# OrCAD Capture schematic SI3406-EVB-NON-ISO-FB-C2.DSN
size B; title: Si3402 Eval Board - Isolated; rev: 2.1; note: SI3406-EVB-NON-ISO-FB-C2
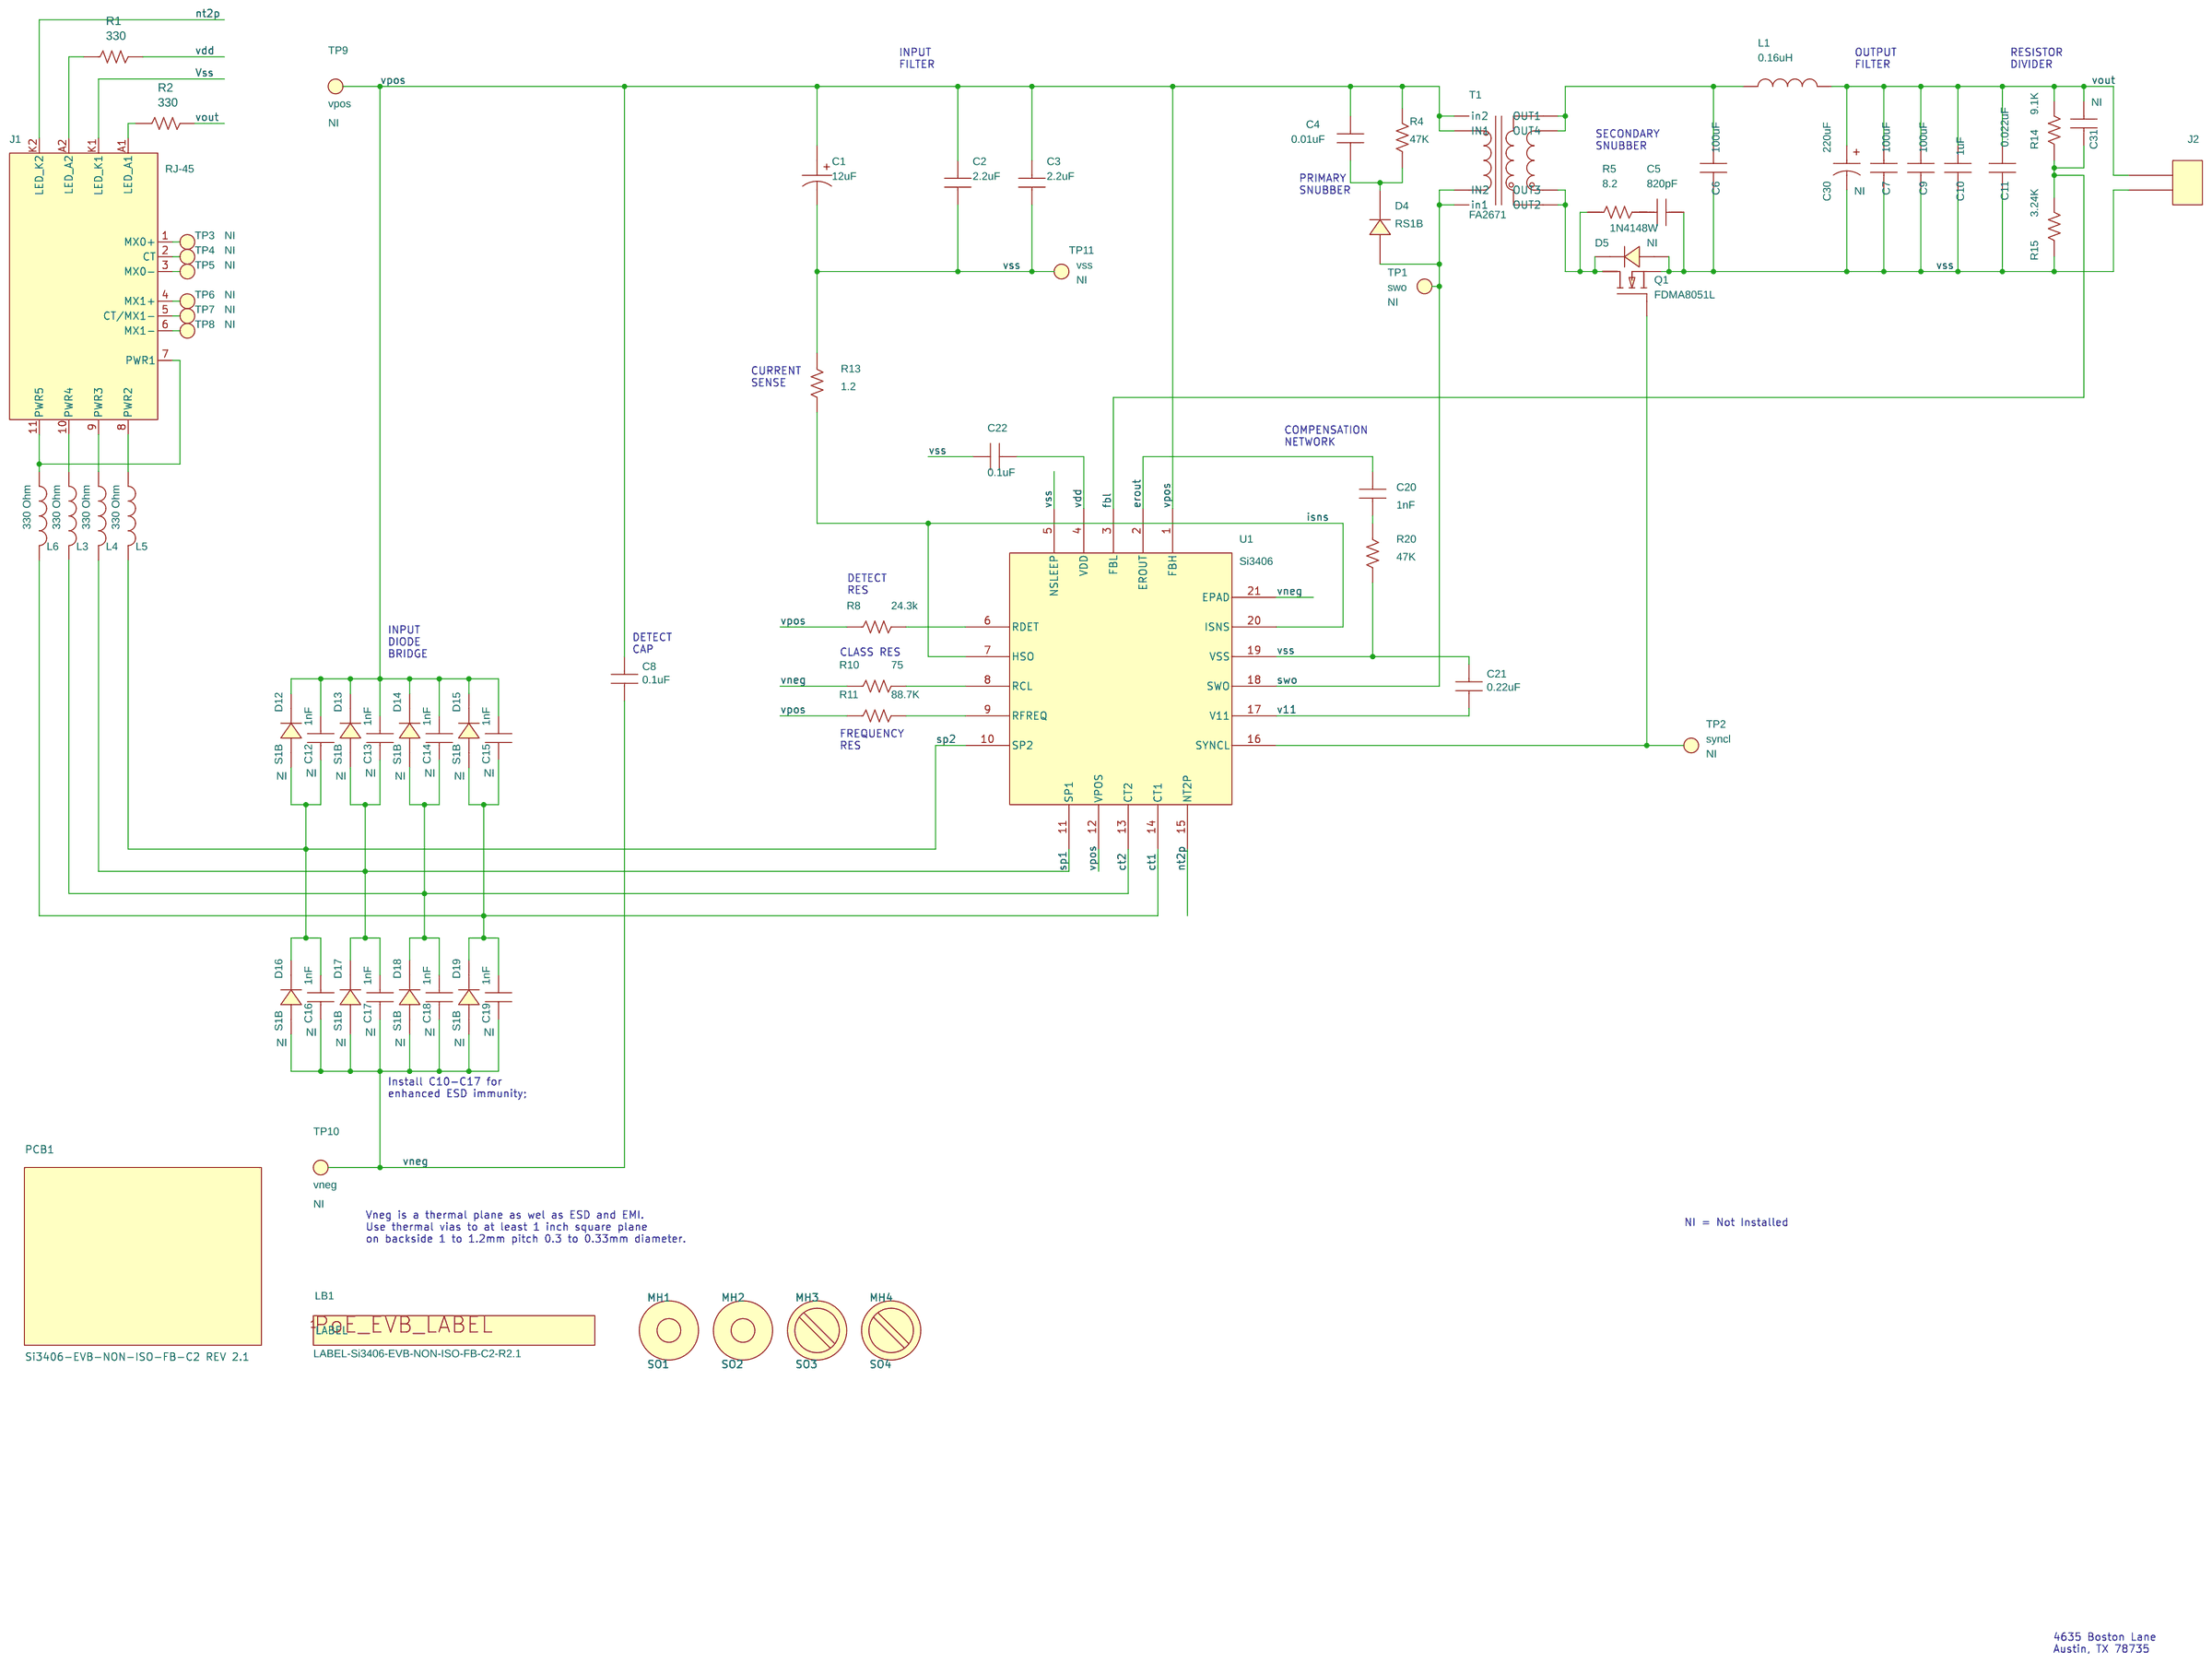
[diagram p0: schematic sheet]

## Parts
C1  12uF  [C2.5X6.3MM-RAD]
C2  2.2uF  [C1210]
C3  2.2uF  [C1210]
C4  0.01uF  [C0805]
C5  820pF  [C0805]
C6  100uF  [C1210]
C7  100uF  [C1210]
C8  0.1uF  [C0805]
C9  100uF  [C1210]
C10  1uF  [C0603]
C11  0.022uF  [C0603]
C12  1nF  [C0603]
C13  1nF  [C0603]
C14  1nF  [C0603]
C15  1nF  [C0603]
C16  1nF  [C0603]
C17  1nF  [C0603]
C18  1nF  [C0603]
C19  1nF  [C0603]
C20  1nF  [C0805]
C21  0.22uF  [C0805]
C22  0.1uF  [C0805]
C30  220uF  [C2X5MM-RAD]
C31  330pF  [C0805]
D4  RS1B  [DO-214AC]
D5  1N4148W  [SOD-123]
D12  S1B  [DO-214AC]
D13  S1B  [DO-214AC]
D14  S1B  [DO-214AC]
D15  S1B  [DO-214AC]
D16  S1B  [DO-214AC]
D17  S1B  [DO-214AC]
D18  S1B  [DO-214AC]
D19  S1B  [DO-214AC]
J1  RJ-45  [RJ45-SI-52004]
J2  CONN TRBLK 2  [CONN-1X2-TB]
L1  0.16uH  [IND-XAL50xx]
L3  330 Ohm  [L0805]
L4  330 Ohm  [L0805]
L5  330 Ohm  [L0805]
L6  330 Ohm  [L0805]
LB1  LABEL-Si3406-EVB-NON-ISO-FB-C2-R2.1  [PTL-14-477]
MH1  4-40  [MH-125NP]
MH2  4-40  [MH-125NP]
MH3  4-40  [MH-125NP]
MH4  4-40  [MH-125NP]
PCB1  Si3406-EVB-NON-ISO-FB-C2 REV 2.1  [N/A]
Q1  FDMA8051L  [DFN6N2X2P0.65E1.0X1.05]
R1  330  [R0805]
R2  330  [R0805]
R4  47K  [R0805]
R5  8.2  [R0805]
R8  24.3k  [R0805]
R10  75  [R0805]
R11  88.7K  [R0805]
R13  1.2  [R0805]
R14  9.1K  [R0805]
R15  3.24K  [R0805]
R20  47K  [R0805]
SO1  STANDOFF
SO2  STANDOFF
SO3  STANDOFF
SO4  STANDOFF
T1  FA2671  [XFMR-FA2671]
TP1  BLUE  [TESTPOINT]
TP2  BLUE  [TESTPOINT]
TP3  BLUE  [TESTPOINT]
TP4  BLUE  [TESTPOINT]
TP5  BLUE  [TESTPOINT]
TP6  BLUE  [TESTPOINT]
TP7  BLUE  [TESTPOINT]
TP8  BLUE  [TESTPOINT]
TP9  BLUE  [TESTPOINT]
TP10  BLUE  [TESTPOINT]
TP11  BLUE  [TESTPOINT]
U1  Si3406  [QFN20N5X5P0.8]

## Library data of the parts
C1 = CAP_POL: CAP, 12uF, 100V, ±20%, AL, 6.3X11.2MM; Manufacturer: Panasonic; ManufacturerPN: EEUFC2A120; Part_Type: CAP/POL; SiLabsPN: EEUFC2A120; Tolerance: ±20%; Type: Alum_Elec; Voltage: 100V; Datasheet: ABA0000CE22.pdf
C2 C3 = CAP_NP: CAP, 2.2uF, 100V, ±10%, X7R, 1210; Manufacturer: Samsung; ManufacturerPN: CL32B225KCJSNNE; SiLabsPN: CL32B225KCJSNNE; Tolerance: ±10%; Type: X7R; Voltage: 100V; Datasheet: MLCC.pdf
C4 = CAP_NP: CAP, 0.01uF, 100V, ±10%, X7R, 0805; Manufacturer: Venkel; ManufacturerPN: C0805X7R101-103K; SiLabsPN: C0805X7R101-103K; Tolerance: ±10%; Type: X7R; Voltage: 100V; Datasheet: PID_C.pdf
C5 = CAP_NP: CAP, 820pF, 50V, ±10%, X7R, 0805; Manufacturer: Yageo; ManufacturerPN: CC0805KRX7R9BB821; SiLabsPN: C0805X7R500-821K; Tolerance: ±10%; Type: X7R; Voltage: 50V; Datasheet: UPY-GPHC_X7R_6.3V-to-50V_18.pdf
C6 C7 C9 = CAP_NP: CAP, 100uF, 6.3V, ±10%, X5R, 1210; Manufacturer: Venkel; ManufacturerPN: C1210X5R6R3-107K; SiLabsPN: C1210X5R6R3-107K; Tolerance: ±10%; Type: X5R; Voltage: 6.3V; Datasheet: PID_C.pdf
C8 C22 = CAP_NP: CAP, 0.1uF, 100V, ±10%, X7R, 0805; Manufacturer: Venkel; ManufacturerPN: C0805X7R101-104K; SiLabsPN: C0805X7R101-104K; Tolerance: ±10%; Type: X7R; Voltage: 100V; Datasheet: PID_C.pdf
C10 = CAP_NP: CAP, 1uF, 6.3V, ±10%, X5R, 0603; Manufacturer: Venkel; ManufacturerPN: C0603X5R6R3-105K; SiLabsPN: C0603X5R6R3-105K; Tolerance: ±10%; Type: X5R; Voltage: 6.3V; Datasheet: PID_C.pdf
C11 = CAP_NP: CAP, 0.022uF, 50V, ±20%, X7R, 0603; Manufacturer: TDK Corporation; ManufacturerPN: C1608X7R1H223M; SiLabsPN: C0603X7R500-223M; Tolerance: ±20%; Type: X7R; Voltage: 50V; Datasheet: general_B11.pdf
C12-C19 = CAP_NP: CAP, 1nF, 100V, ±10%, X7R, 0603; Installed Component: NI; Manufacturer: Venkel; ManufacturerPN: C0603X7R101-102K; SiLabsPN: C0603X7R101-102K; Tolerance: ±10%; Type: X7R; Voltage: 100V; Datasheet: PID_C.pdf
C20 = CAP_NP: CAP, 1nF, 50V, ±1%, C0G, 0805; Manufacturer: Venkel; ManufacturerPN: C0805C0G500-102F; SiLabsPN: C0805C0G500-102F; Tolerance: ±1%; Type: C0G; Voltage: 50V; Datasheet: PID_C.pdf
C21 = CAP_NP: CAP, 0.22uF, 10V, ±10%, X7R, 0805; Manufacturer: Venkel; ManufacturerPN: C0805X7R100-224K; SiLabsPN: C0805X7R100-224K; Tolerance: ±10%; Type: X7R; Voltage: 10V; Datasheet: PID_C.pdf
C30 = CAP_POL_ALT: CAP, 220uF, 6.3V, ±20%, AL, RAD; FPLIST: C2X5MM-RAD,C2.0X5MM-RAD; Installed Component: NI; Manufacturer: Panasonic; ManufacturerPN: ECA0JM221; SiLabsPN: ECA0JM221; Tolerance: ±20%; Type: Alum_Elec; Voltage: 6.3V; Datasheet: ABA0000CE12.pdf
C31 = CAP_NP: CAP, 330pF, 100V, ±20%, X7R, 0805; Installed Component: NI; Manufacturer: Venkel; ManufacturerPN: C0805X7R101-331M; SiLabsPN: C0805X7R101-331M; Tolerance: ±20%; Type: X7R; Voltage: 100V; Datasheet: PID_C.pdf
D4 = DIODE: DIO, SINGLE, 100V, 1.0A, SMA; Manufacturer: Fairchild; Rating: 1.0A; Type: Single; Voltage: 100V; Datasheet: RS1A.pdf
D5 = DIODE: DIO, SINGLE, 100V, 300mA, SOD123; Installed Component: NI; Manufacturer: Diodes Inc.; ManufacturerPN: 1N4148W-7-F; Rating: 300mA; SiLabsPN: 1N4148W-7-F; Type: Single; Voltage: 100V; Datasheet: ds30086.pdf
D12-D19 = DIODE: DIO, SINGLE, 100V, 1.0A, SMA; Installed Component: NI; Manufacturer: Fairchild; Rating: 1.0A; Type: Single; Voltage: 100V; Datasheet: S1A.pdf
J1 = MAGJACK_3: CONN, RJ-45, MAGJACK, 1 Port PoE; Manufacturer: Bel; ManufacturerPN: SI-52003-F; SiLabsPN: SI-52003-F; Type: Receptacle; Datasheet: SI-52003-F.pdf
J2 = CONN_TRBLK_2: CONN, TERM BLOCK 2POS, 5MM PCB; Manufacturer: PHOENIX CONTACT; ManufacturerPN: 1729018; SiLabsPN: 1729018; Type: TERM BLK; Datasheet: 1729018.pdf
L1 = INDUCTOR: INDUCTOR, POWER, Shielded, 0.16uH, 31A, SMD; Manufacturer: Coilcraft; ManufacturerPN: XAL5030-161ME; Rating: 16A; SiLabsPN: XAL5030-161ME; Tolerance: ±20%; Type: Shielded; Datasheet: xal50xx-270657.pdf
L3-L6 = Ferrite_Bead: FERRITE BEAD, 330 Ohm @100MHZ, 0805; Manufacturer: MuRata; ManufacturerPN: BLM21PG331SN1; Part_Type: IND/FB; Rating: 1500mA; SiLabsPN: BLM21PG331SN1; Type: SMT; Datasheet: Murata BLM Ferrites.pdf
LB1 = PoE_EVB_Label: LABEL, PDB, POLYIMIDE, WHITE, 1.00 in. X 0.187 in., FONT 2; Manufacturer: Skyworks; Type: POLYIMIDE, WHITE; Datasheet: Brady TLS2200 Label PTL-14-477.pdf
MH1-MH4 = SCREW-Small: HDW, SCREW, 4-40 x 1/4 in. Pan Head, Slotted, Nylon; Manufacturer: Richco Plastic Co; ManufacturerPN: NSS-4-4-01; SiLabsPN: NSS-4-4-01; Type: SCREW; Datasheet: RichcoPlasticCo_Screws.pdf
PCB1 = PCB: PCB, BARE BOARD, Si3406-EVB-NON-ISO-FB-C2 REV 2.1; Manufacturer: Skyworks; Type: BARE PCB
Q1 = NFET_DDGSDDD: TRANSISTOR, MOSFET, N-CHNL, 40V, 10A, 2.4W Switching Logic Level, SMT; Manufacturer: Fairchild; Rating: 10A; Type: N-CHNL; Voltage: 40V; Datasheet: FDMA8051L.pdf
R1 R2 = RES_V: RES, 330 Ohm, 1/10W, ±1%, ThickFilm, 0805; Manufacturer: Venkel; ManufacturerPN: CR0805-10W-3300F; Part_Type: RES/SMT; Rating: 1/10W; SiLabsPN: CR0805-10W-3300F; Tolerance: ±1%; Type: ThickFilm; Datasheet: PID_CR.pdf
R4 R20 = RES: RES, 47K, 1/10W, ±5%, ThickFilm, 0805; Manufacturer: Venkel; ManufacturerPN: CR0805-10W-473J; Rating: 1/10W; SiLabsPN: CR0805-10W-473J; Tolerance: ±5%; Type: ThickFilm; Datasheet: PID_CR.pdf
R5 = RES: RES, 8.2 Ohm, 1/8W, ±1%, ThickFilm, 0805; Manufacturer: Yageo; ManufacturerPN: RC0805FR-078R2L; Rating: 1/8W; SiLabsPN: CR0805-8W-8R20F; Tolerance: ±1%; Type: ThickFilm; Datasheet: PYu-RC_Group_51_RoHS_L_8.pdf
R8 = RES: RES, 24.3k, 1/8W, ±1%, ThickFilm, 0805; Manufacturer: vishay; ManufacturerPN: CRCW080524K3FKEA; Rating: 1/8W; SiLabsPN: CR0805-8W-2432F; Tolerance: ±1%; Type: ThickFilm; Datasheet: dcrcwe3-109170.pdf
R10 = RES: RES, 75 Ohm, 1/10W, ±1%, ThickFilm, 0805; Manufacturer: Venkel; ManufacturerPN: CR0805-10W-75R0F; Rating: 1/10W; SiLabsPN: CR0805-10W-75R0F; Tolerance: ±1%; Type: ThickFilm; Datasheet: PID_CR.pdf
R11 = RES: RES, 88.7K, 1/8W, ±1%, ThickFilm, 0805; Manufacturer: Vishay; ManufacturerPN: CRCW080588K7FKEA; Rating: 1/8W; SiLabsPN: CR0805-8W-8872F; Tolerance: ±1%; Type: ThickFilm; Datasheet: dcrcwe3-109170.pdf
R13 = RES: RES, 1.2 Ohm, 1/10W, ±5%, ThickFilm, 0805; Manufacturer: Venkel; ManufacturerPN: CR0805-10W-1R2J; Rating: 1/10W; SiLabsPN: CR0805-10W-1R2J; Tolerance: ±5%; Type: ThickFilm; Datasheet: PID_CR.pdf
R14 = RES: RES, 9.1K, 1/8W, ±1%, ThickFilm, 0805; Manufacturer: Yageo; ManufacturerPN: RC0805FR-079K1L; Rating: 1/8W; SiLabsPN: CR0805-8W-9101F; Tolerance: ±1%; Type: ThickFilm; Datasheet: PYu-RC_Group_51_RoHS_L_8.pdf
R15 = RES: RES, 3.24K, 1/8W, ±1%, ThickFilm, 0805; Manufacturer: Vishay; ManufacturerPN: CRCW08053K24FKEA; Rating: 1/8W; SiLabsPN: CR0805-8W-3241F; Tolerance: ±1%; Type: ThickFilm; Datasheet: dcrcwe3-109170.pdf
SO1-SO4 = STANDOFF: HDW, STANDOFF, 4-40 X 1/2" , Nylon; Manufacturer: SPC Technology; ManufacturerPN: 2397; SiLabsPN: 2397; Datasheet: SPC_Technology_spacers.pdf
T1 = XFMR_FA2671: TRANSFORMER, FLYBACK, 40uH PRIMARY, 0.395uH LEAKAGE, 1:0.3, 10W, 3.3V, SMT; Manufacturer: Coilcraft; Rating: 10W; Datasheet: fa2671.pdf
TP1 = TEST_POINT: TESTPOINT, BLUE, PTH; Installed Component: NI; Manufacturer: Kobiconn; ManufacturerPN: 151-205-RC; SiLabsPN: 151-205; Silk: swo; Type: Loop; Datasheet: KC-300780.pdf
TP2 = TEST_POINT: TESTPOINT, BLUE, PTH; Installed Component: NI; Manufacturer: Kobiconn; ManufacturerPN: 151-205-RC; SiLabsPN: 151-205; Silk: syncl; Type: Loop; Datasheet: KC-300780.pdf
TP3-TP8 = TEST_POINT: TESTPOINT, BLUE, PTH; Installed Component: NI; Manufacturer: Kobiconn; ManufacturerPN: 151-205-RC; SiLabsPN: 151-205; Type: Loop; Datasheet: KC-300780.pdf
TP9 = TEST_POINT: TESTPOINT, BLUE, PTH; Installed Component: NI; Manufacturer: Kobiconn; ManufacturerPN: 151-205-RC; SiLabsPN: 151-205; Silk: vpos; Type: Loop; Datasheet: KC-300780.pdf
TP10 = TEST_POINT: TESTPOINT, BLUE, PTH; Installed Component: NI; Manufacturer: Kobiconn; ManufacturerPN: 151-205-RC; SiLabsPN: 151-205; Silk: vneg; Type: Loop; Datasheet: KC-300780.pdf
TP11 = TEST_POINT: TESTPOINT, BLUE, PTH; Installed Component: NI; Manufacturer: Kobiconn; ManufacturerPN: 151-205-RC; SiLabsPN: 151-205; Silk: vss; Type: Loop; Datasheet: KC-300780.pdf
U1 = Si3406: IC, FULLY-INTEGRATED 802.3-COMPLIANT PoE PD INTERFACE AND LOW-EMI SWITCHING REGULATOR, QFN20; Manufacturer: Skyworks; ManufacturerPN: Si3406-A-GM; SiLabsPN: Si3406-A-GM; Type: PD; Voltage: 120V; Datasheet: si3406x-datasheet.pdf

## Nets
v11: C21.2 U1.17(V11)
vdd: C22.2 R1.1 U1.4(VDD)
Vss: C1.2 C2.1 C3.1 C5.2 C6.2 C7.2 C9.2 C10.2 C11.2 C21.1 C22.1 C30.2 D5.A(ANODE) J1.K1(LED) J2.1 Q1.S(SOURCE) R13.1 R15.1 R20.2 TP11.1(Point) U1.5(NSLEEP) U1.19(VSS)
ct1: C15.1 C19.2 D15.A(ANODE) D19.K(CATHODE) L6.2 U1.14(CT1)
ct2: C14.1 C18.2 D14.A(ANODE) D18.K(CATHODE) L3.2 U1.13(CT2)
erout: C20.2 U1.2(EROUT)
fbl: C31.2 R14.1 R15.2 U1.3(FBL)
isns: R13.2 U1.7(HSO) U1.20(ISNS)
LABEL: LB1.1(LABEL)
nt2p: J1.K2(LED) U1.15(NT2P)
sp1: C13.1 C17.2 D13.A(ANODE) D17.K(CATHODE) L4.2 U1.11(SP1)
sp2: C12.1 C16.2 D12.A(ANODE) D16.K(CATHODE) L5.2 U1.10(SP2)
swo: D4.A(ANODE) T1.1(in1) T1.2(IN2) TP1.1(Point) U1.18(SWO)
vneg: C8.2 C16.1 C17.1 C18.1 C19.1 D16.A(ANODE) D17.A(ANODE) D18.A(ANODE) D19.A(ANODE) R10.1 TP10.1(Point) U1.21(EPAD)
vout: C7.1 C9.1 C10.1 C11.1 C30.1 C31.1 J2.2 L1.2 R2.1 R14.2
vpos: C1.1 C2.2 C3.2 C4.1 C8.1 C12.2 C13.2 C14.2 C15.2 D12.K(CATHODE) D13.K(CATHODE) D14.K(CATHODE) D15.K(CATHODE) R4.2 R8.1 R11.1 T1.3(IN1) T1.4(in2) TP9.1(Point) U1.1(FBH) U1.12(VPOS)
N317144: J1.A1(LED) R2.2
N1344300: J1.A2(LED) R1.2
N1417624: J1.7(PWR1) J1.11(PWR5) L6.1
N1446659: C4.2 D4.K(CATHODE) R4.1
N1453435: D5.K(CATHODE) Q1.D1(DRAIN) Q1.D2(DRAIN) Q1.D3(DRAIN) Q1.D4(DRAIN) Q1.D5(DRAIN) R5.1 T1.5(OUT2) T1.6(OUT3)
N1476158: Q1.G(GATE) TP2.1(Point) U1.16(SYNCL)
N1484477: R11.2 U1.9(RFREQ)
N1498307: C6.1 L1.1 T1.7(OUT1) T1.8(OUT4)
N1505711: J1.1(MX0+) TP3.1(Point)
N1505935: J1.6(MX1-) TP8.1(Point)
N1505939: J1.5(CT/MX1-) TP7.1(Point)
N1505943: J1.4(MX1+) TP6.1(Point)
N1505947: J1.3(MX0-) TP5.1(Point)
N1505951: J1.2(CT) TP4.1(Point)
N1524736: C5.1 R5.2
N1527876: J1.8(PWR2) L5.1
N1527880: J1.9(PWR3) L4.1
N1527949: J1.10(PWR4) L3.1
N1548116: C20.1 R20.1
N1593612: R8.2 U1.6(RDET)
N1594097: R10.2 U1.8(RCL)

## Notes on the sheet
- INPUT
  FILTER
- OUTPUT
  FILTER
- RESISTOR
  DIVIDER
- SECONDARY
  SNUBBER
- PRIMARY
  SNUBBER
- CURRENT
  SENSE
- COMPENSATION
  NETWORK
- DETECT
  RES
- INPUT
  DIODE
  BRIDGE
- DETECT
  CAP
- CLASS RES
- FREQUENCY
  RES
- Install C10-C17 for
  enhanced ESD immunity;
- Vneg is a thermal plane as wel as ESD and EMI.
  Use thermal vias to at least 1 inch square plane
  on backside 1 to 1.2mm pitch 0.3 to 0.33mm diameter.
- NI = Not Installed
- 4635 Boston Lane
  Austin, TX 78735
